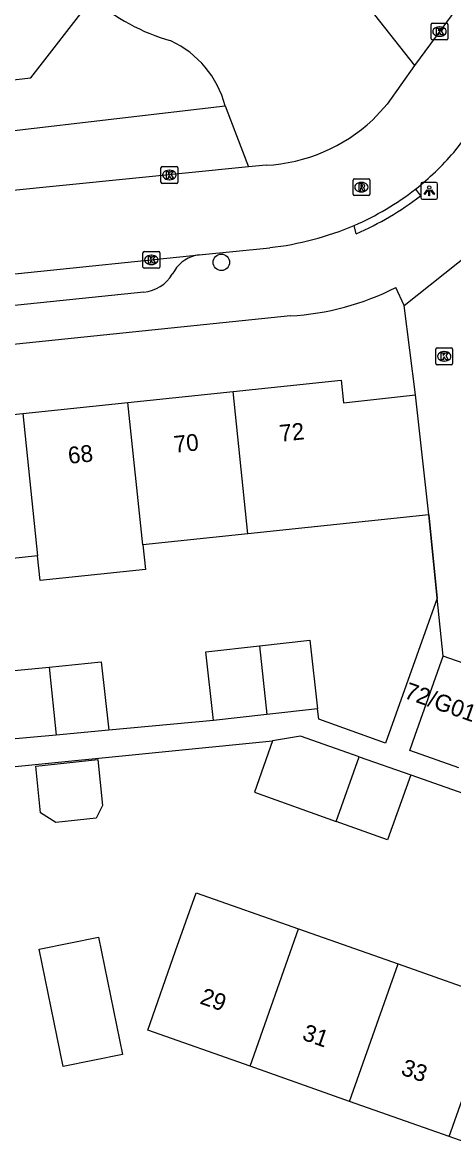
# Model space of a CAD drawing. Extents: x 160557 to 161245, y 385330 to 386505.
# Drawn here: x 160836.9 to 160862.6, y 385939.3 to 386005.8 of the extents above; entities that cross this region are included whole.
import ezdxf

# ---------------------------------------------------------------- set-up
doc = ezdxf.new("R2010")
doc.units = 0
for name, color, linetype in [('IMGEO_Boom', 7, 'Continuous'), ('IMGEO_Groenvoorziening', 7, 'Continuous'), ('IMGEO_Kolk', 7, 'Continuous'), ('IMGEO_Lichtpunt', 7, 'Continuous'), ('IMGEO_Muur', 7, 'Continuous'), ('IMGEO_Pand', 7, 'Continuous'), ('IMGEO_Pand_nummerreeks', 7, 'Continuous'), ('IMGEO_Rijbaan_lokaal_open', 7, 'Continuous'), ('IMGEO_Rioolput', 7, 'Continuous'), ('IMGEO_Voetpad_open', 7, 'Continuous')]:
    doc.layers.add(name, color=color, linetype=linetype)

msp = doc.modelspace()

# ---------------------------------------------------------------- linework, layer by layer
at = {"layer": 'IMGEO_Boom'}
msp.add_circle((160848.786, 385991.504), 0.489, dxfattribs=at)
at = {"layer": 'IMGEO_Groenvoorziening'}
for points in [[(160810.264, 385996.293), (160810.045, 385999.398), (160815.371, 386000), (160837.444, 386002.495), (160841.108, 386007.247)], [(160810.264, 385996.293), (160849.009, 386000.831)]]:
    msp.add_lwpolyline(points, dxfattribs=at)
at = {"layer": 'IMGEO_Kolk'}
for p, q in [((160861.283, 386004.824), (160861.283, 386005.676)), ((160861.358, 386005.75), (160862.21, 386005.75)), ((160861.771, 386005.53), (160861.796, 386005.53)), ((160862.284, 386005.676), (160862.284, 386004.824)), ((160861.794, 386004.97), (160861.769, 386004.97)), ((160862.21, 386004.75), (160861.358, 386004.75)), ((160845.188, 385996.282), (160845.188, 385997.134)), ((160845.263, 385997.208), (160846.115, 385997.208)), ((160845.676, 385996.988), (160845.701, 385996.988)), ((160846.189, 385997.134), (160846.189, 385996.282)), ((160846.115, 385996.208), (160845.263, 385996.208)), ((160845.699, 385996.428), (160845.674, 385996.428)), ((160844.192, 385992.151), (160845.044, 385992.151)), ((160844.117, 385991.225), (160844.117, 385992.077)), ((160844.605, 385991.931), (160844.63, 385991.931)), ((160845.118, 385992.077), (160845.118, 385991.225)), ((160845.044, 385991.151), (160844.192, 385991.151)), ((160844.628, 385991.371), (160844.603, 385991.371)), ((160861.563, 385985.478), (160861.563, 385986.33)), ((160861.638, 385986.404), (160862.49, 385986.404)), ((160862.051, 385986.184), (160862.076, 385986.184)), ((160862.564, 385986.33), (160862.564, 385985.478)), ((160862.074, 385985.624), (160862.049, 385985.624)), ((160862.49, 385985.404), (160861.638, 385985.404))]:
    msp.add_line(p, q, dxfattribs=at)
for points in [[(160861.283, 386004.824), (160861.283, 386005.676)], [(160861.358, 386005.75), (160862.21, 386005.75)], [(160861.604, 386005.45), (160861.727, 386005.45), (160861.727, 386005.299), (160861.857, 386005.45), (160862.021, 386005.45), (160861.875, 386005.299), (160862.028, 386005.05), (160861.876, 386005.05), (160861.791, 386005.214), (160861.727, 386005.147), (160861.727, 386005.05), (160861.604, 386005.05), (160861.604, 386005.45)], [(160862.284, 386005.676), (160862.284, 386004.824)], [(160862.21, 386004.75), (160861.358, 386004.75)], [(160845.188, 385996.282), (160845.188, 385997.134)], [(160845.263, 385997.208), (160846.115, 385997.208)], [(160845.509, 385996.908), (160845.632, 385996.908), (160845.632, 385996.757), (160845.762, 385996.908), (160845.926, 385996.908), (160845.78, 385996.757), (160845.933, 385996.508), (160845.781, 385996.508), (160845.696, 385996.672), (160845.632, 385996.605), (160845.632, 385996.508), (160845.509, 385996.508), (160845.509, 385996.908)], [(160846.189, 385997.134), (160846.189, 385996.282)], [(160846.115, 385996.208), (160845.263, 385996.208)], [(160844.192, 385992.151), (160845.044, 385992.151)], [(160844.117, 385991.225), (160844.117, 385992.077)], [(160844.438, 385991.851), (160844.561, 385991.851), (160844.561, 385991.7), (160844.691, 385991.851), (160844.855, 385991.851), (160844.709, 385991.7), (160844.862, 385991.451), (160844.71, 385991.451), (160844.625, 385991.615), (160844.561, 385991.548), (160844.561, 385991.451), (160844.438, 385991.451), (160844.438, 385991.851)], [(160845.118, 385992.077), (160845.118, 385991.225)], [(160845.044, 385991.151), (160844.192, 385991.151)], [(160861.563, 385985.478), (160861.563, 385986.33)], [(160861.638, 385986.404), (160862.49, 385986.404)], [(160862.564, 385986.33), (160862.564, 385985.478)], [(160861.884, 385986.104), (160862.007, 385986.104), (160862.007, 385985.953), (160862.137, 385986.104), (160862.301, 385986.104), (160862.155, 385985.953), (160862.308, 385985.704), (160862.156, 385985.704), (160862.071, 385985.868), (160862.007, 385985.801), (160862.007, 385985.704), (160861.884, 385985.704), (160861.884, 385986.104)], [(160862.49, 385985.404), (160861.638, 385985.404)]]:
    msp.add_lwpolyline(points, dxfattribs=at)
for centre, start, end in [((160861.36, 386005.674), 91.55205, 178.44795), ((160861.36, 386005.674), 91.55205, 178.44795), ((160862.208, 386005.674), 1.55205, 88.44795), ((160862.208, 386005.674), 1.55205, 88.44795), ((160861.36, 386004.826), 181.55205, 268.44795), ((160861.36, 386004.826), 181.55205, 268.44795), ((160862.208, 386004.826), 271.55205, 358.44795), ((160862.208, 386004.826), 271.55205, 358.44795), ((160845.265, 385997.132), 91.55205, 178.44795), ((160845.265, 385997.132), 91.55205, 178.44795), ((160846.113, 385997.132), 1.55205, 88.44795), ((160846.113, 385997.132), 1.55205, 88.44795), ((160845.265, 385996.284), 181.55205, 268.44795), ((160845.265, 385996.284), 181.55205, 268.44795), ((160846.113, 385996.284), 271.55205, 358.44795), ((160846.113, 385996.284), 271.55205, 358.44795), ((160844.194, 385992.075), 91.55205, 178.44795), ((160844.194, 385992.075), 91.55205, 178.44795), ((160845.042, 385992.075), 1.55205, 88.44795), ((160845.042, 385992.075), 1.55205, 88.44795), ((160844.194, 385991.227), 181.55205, 268.44795), ((160844.194, 385991.227), 181.55205, 268.44795), ((160845.042, 385991.227), 271.55205, 358.44795), ((160845.042, 385991.227), 271.55205, 358.44795), ((160861.64, 385986.328), 91.55205, 178.44795), ((160861.64, 385986.328), 91.55205, 178.44795), ((160862.488, 385986.328), 1.55205, 88.44795), ((160862.488, 385986.328), 1.55205, 88.44795), ((160861.64, 385985.48), 181.55205, 268.44795), ((160861.64, 385985.48), 181.55205, 268.44795), ((160862.488, 385985.48), 271.55205, 358.44795), ((160862.488, 385985.48), 271.55205, 358.44795)]:
    msp.add_arc(centre, 0.0765, start, end, dxfattribs=at)
for centre, major_axis, ratio, start_param, end_param in [((160861.77, 386005.25), (-0.387, 0.002), 0.722429, 4.712389, 7.853982), ((160861.795, 386005.25), (-0.39, 0.002), 0.717154, 1.570796, 4.712389), ((160845.675, 385996.708), (-0.387, 0.002), 0.722429, 4.712389, 7.853982), ((160845.7, 385996.708), (-0.39, 0.002), 0.717154, 1.570796, 4.712389), ((160844.604, 385991.651), (-0.387, 0.002), 0.722429, 4.712389, 7.853982), ((160844.629, 385991.651), (-0.39, 0.002), 0.717154, 1.570796, 4.712389), ((160862.05, 385985.904), (-0.387, 0.002), 0.722429, 4.712389, 7.853982), ((160862.075, 385985.904), (-0.39, 0.002), 0.717154, 1.570796, 4.712389)]:
    msp.add_ellipse(centre, major_axis=major_axis, ratio=ratio, start_param=start_param, end_param=end_param, dxfattribs=at)
at = {"layer": 'IMGEO_Lichtpunt'}
for p, q in [((160860.674, 385996.164), (160860.674, 385995.357)), ((160860.674, 385996.164), (160860.674, 385995.357)), ((160861.576, 385996.259), (160860.768, 385996.259)), ((160861.576, 385996.259), (160860.768, 385996.259)), ((160861.67, 385995.357), (160861.67, 385996.164)), ((160861.67, 385995.357), (160861.67, 385996.164)), ((160860.768, 385995.263), (160861.576, 385995.263)), ((160860.768, 385995.263), (160861.576, 385995.263))]:
    msp.add_line(p, q, dxfattribs=at)
for points in [[(160861.048, 385995.828), (160861.087, 385995.8), (160860.899, 385995.538), (160860.861, 385995.565), (160861.048, 385995.828)], [(160861.15, 385995.78), (160861.197, 385995.78), (160861.197, 385995.458), (160861.15, 385995.458), (160861.15, 385995.78)], [(160861.26, 385995.8), (160861.298, 385995.827), (160861.485, 385995.565), (160861.446, 385995.537), (160861.26, 385995.8)]]:
    msp.add_lwpolyline(points, dxfattribs=at)
msp.add_circle((160861.173, 385995.962), 0.0994, dxfattribs=at)
for centre, start, end in [((160860.768, 385996.164), 90, 180), ((160860.768, 385996.164), 90, 180), ((160861.576, 385996.164), 0, 90), ((160861.576, 385996.164), 0, 90), ((160860.768, 385995.357), 180, 270), ((160860.768, 385995.357), 180, 270), ((160861.576, 385995.357), 270, 0), ((160861.576, 385995.357), 270, 360)]:
    msp.add_arc(centre, 0.0946, start, end, dxfattribs=at)
at = {"layer": 'IMGEO_Muur'}
for points in [[(160861.144, 385976.456), (160861.645, 385971.496)], [(160861.645, 385971.496), (160858.563, 385962.869)]]:
    msp.add_lwpolyline(points, dxfattribs=at)
at = {"layer": 'IMGEO_Pand'}
for points in [[(160849.487, 385983.818), (160855.932, 385984.491), (160856.074, 385983.14), (160860.359, 385983.611)], [(160843.218, 385983.163), (160849.487, 385983.818)], [(160850.373, 385975.327), (160849.487, 385983.818)], [(160861.144, 385976.456), (160860.359, 385983.611)], [(160836.949, 385982.508), (160843.218, 385983.163)], [(160844.104, 385974.67), (160843.218, 385983.163)], [(160830.68, 385981.854), (160836.949, 385982.508)], [(160836.949, 385982.508), (160837.836, 385974.012)], [(160861.144, 385976.456), (160850.373, 385975.327)], [(160850.373, 385975.327), (160844.104, 385974.67)], [(160844.104, 385974.67), (160844.257, 385973.205), (160837.989, 385972.55), (160837.836, 385974.012)], [(160837.836, 385974.012), (160831.567, 385973.355)], [(160851.067, 385968.668), (160854.059, 385969.003), (160854.517, 385964.909)], [(160848.319, 385964.215), (160847.861, 385968.309), (160851.067, 385968.668)], [(160851.067, 385968.668), (160851.495, 385964.571)], [(160838.526, 385967.397), (160841.634, 385967.701), (160842.089, 385963.638)], [(160862.927, 385961.397), (160860.013, 385962.422), (160860.334, 385963.334), (160861.993, 385968.05)], [(160864.907, 385967.025), (160861.993, 385968.05)], [(160835.849, 385963.06), (160835.398, 385967.092), (160838.526, 385967.397)], [(160838.526, 385967.397), (160838.948, 385963.347)], [(160854.517, 385964.909), (160851.495, 385964.571)], [(160851.495, 385964.571), (160848.319, 385964.215)], [(160842.089, 385963.638), (160838.948, 385963.347)], [(160838.948, 385963.347), (160835.849, 385963.06)], [(160851.843, 385963.002), (160850.755, 385959.949), (160855.636, 385958.193)], [(160856.999, 385962.054), (160853.51, 385963.283), (160851.843, 385963.002)], [(160837.724, 385961.499), (160841.426, 385961.884), (160841.71, 385959.151), (160841.328, 385958.389), (160838.916, 385958.137), (160838.015, 385958.71), (160837.724, 385961.499)], [(160855.636, 385958.193), (160856.999, 385962.054)], [(160856.999, 385962.054), (160860.069, 385960.973)], [(160860.069, 385960.973), (160858.687, 385957.096), (160855.636, 385958.193)], [(160850.495, 385943.621), (160844.396, 385945.773), (160846.06, 385950.488), (160847.284, 385953.956), (160853.382, 385951.804)], [(160850.495, 385943.621), (160853.382, 385951.804)], [(160853.382, 385951.804), (160859.317, 385949.71)], [(160837.928, 385950.586), (160841.461, 385951.312), (160842.896, 385944.323), (160839.364, 385943.597), (160837.928, 385950.586)], [(160856.43, 385941.526), (160859.317, 385949.71)], [(160859.317, 385949.71), (160865.253, 385947.615)], [(160862.365, 385939.432), (160865.253, 385947.615)], [(160856.43, 385941.526), (160850.495, 385943.621)], [(160862.365, 385939.432), (160856.43, 385941.526)], [(160868.3, 385937.337), (160862.365, 385939.432)]]:
    msp.add_lwpolyline(points, dxfattribs=at)
at = {"layer": 'IMGEO_Rijbaan_lokaal_open'}
for points in [[(160874.196, 386022.067), (160860.296, 386003.233)], [(160860.296, 386003.233), (160858.671, 386000.925), (160857.806, 386000)], [(160862.629, 385998.05), (160864.17, 386000.025), (160864.278, 386000.17)], [(160850.396, 385997.184), (160810.482, 385993.187)], [(160851.454, 385997.29), (160850.396, 385997.184)], [(160847.456, 385991.944), (160851.678, 385992.378)], [(160788.954, 385985.976), (160801.932, 385987.281), (160825.874, 385989.726), (160847.456, 385991.944)], [(160859.687, 385988.936), (160863.654, 385992.093)], [(160860.359, 385983.611), (160859.687, 385988.936)], [(160861.645, 385971.496), (160861.144, 385976.456)], [(160861.993, 385968.05), (160861.645, 385971.496)]]:
    msp.add_lwpolyline(points, dxfattribs=at)
for centre, radius, start, end in [((160850.956, 386007.256), 9.978, 272.85933, 313.35047), ((160850.31, 386008.607), 16.224, 308.25527, 319.4054), ((160849.778, 386009.535), 17.283, 293.64451, 307.73606), ((160849.601, 386010.48), 18.22, 276.54673, 292.96281)]:
    msp.add_arc(centre, radius, start, end, dxfattribs=at)
at = {"layer": 'IMGEO_Rioolput'}
for p, q in [((160856.631, 385995.556), (160856.631, 385996.408)), ((160856.706, 385996.482), (160857.558, 385996.482)), ((160857.119, 385996.262), (160857.144, 385996.262)), ((160857.632, 385996.408), (160857.632, 385995.556)), ((160857.558, 385995.482), (160856.706, 385995.482)), ((160857.142, 385995.702), (160857.117, 385995.702))]:
    msp.add_line(p, q, dxfattribs=at)
for points in [[(160856.631, 385995.556), (160856.631, 385996.408)], [(160856.706, 385996.482), (160857.558, 385996.482)], [(160857.22, 385996.18), (160856.968, 385996.182), (160856.968, 385995.782)], [(160857.632, 385996.408), (160857.632, 385995.556)], [(160857.558, 385995.482), (160856.706, 385995.482)], [(160856.968, 385995.782), (160857.092, 385995.782), (160857.092, 385995.944), (160857.103, 385995.944)], [(160857.146, 385996.101), (160857.092, 385996.101), (160857.092, 385996.02)], [(160857.092, 385996.02), (160857.144, 385996.02)], [(160857.15, 385995.915), (160857.221, 385995.782), (160857.361, 385995.782), (160857.296, 385995.908)]]:
    msp.add_lwpolyline(points, dxfattribs=at)
for centre, radius, start, end in [((160856.708, 385996.406), 0.0765, 91.55205, 178.44795), ((160856.708, 385996.406), 0.0765, 91.55205, 178.44795), ((160857.219, 385996.07), 0.109, 350.36119, 89.41601), ((160857.556, 385996.406), 0.0765, 1.55205, 88.44795), ((160857.556, 385996.406), 0.0765, 1.55205, 88.44795), ((160856.708, 385995.558), 0.0765, 181.55205, 268.44795), ((160856.708, 385995.558), 0.0765, 181.55205, 268.44795), ((160857.102, 385995.891), 0.0533, 26.02933, 88.69889), ((160857.128, 385996.209), 0.19, 274.7715, 282.96867), ((160857.152, 385996.005), 0.0964, 77.00612, 93.18647), ((160857.166, 385996.062), 0.0378, 276.66336, 79.67722), ((160857.217, 385996.07), 0.112, 277.58423, 350.98172), ((160857.201, 385995.855), 0.108, 29.51342, 73.79051), ((160857.556, 385995.558), 0.0765, 271.55205, 358.44795), ((160857.556, 385995.558), 0.0765, 271.55205, 358.44795)]:
    msp.add_arc(centre, radius, start, end, dxfattribs=at)
for centre, major_axis, ratio, start_param, end_param in [((160857.118, 385995.982), (-0.387, 0.002), 0.722429, 4.712389, 7.853982), ((160857.143, 385995.982), (-0.39, 0.002), 0.717154, 1.570796, 4.712389)]:
    msp.add_ellipse(centre, major_axis=major_axis, ratio=ratio, start_param=start_param, end_param=end_param, dxfattribs=at)
at = {"layer": 'IMGEO_Voetpad_open'}
for points in [[(160857.022, 386007.394), (160860.296, 386003.233)], [(160849.009, 386000.831), (160849.325, 386000), (160850.396, 385997.184)], [(160860.355, 385995.867), (160860.645, 385995.46)], [(160856.827, 385993.209), (160856.709, 385993.703)], [(160845.993, 385991.005), (160845.862, 385990.792)], [(160844.175, 385989.732), (160826.064, 385987.871), (160802.12, 385985.425), (160792.445, 385984.458)], [(160859.687, 385988.936), (160859.181, 385990.012)], [(160852.902, 385988.314), (160784.881, 385981.295)], [(160861.645, 385971.496), (160858.563, 385962.869), (160854.6, 385964.296), (160854.517, 385964.909)], [(160848.319, 385964.215), (160842.089, 385963.638)], [(160829.319, 385960.753), (160851.843, 385963.002)], [(160860.069, 385960.973), (160865.99, 385958.889)]]:
    msp.add_lwpolyline(points, dxfattribs=at)
for centre, radius, start, end in [((160849.114, 386016.345), 12.119, 228.65351, 254.06209), ((160843.291, 385999.334), 5.911, 14.67413, 65.03328), ((160849.799, 386009.492), 17.735, 293.34441, 307.70072), ((160847.696, 385989.961), 1.998, 96.89944, 148.48784), ((160843.945, 385991.971), 2.25, 275.86725, 328.41786), ((160852.037, 386003.972), 15.682, 273.16265, 297.10191)]:
    msp.add_arc(centre, radius, start, end, dxfattribs=at)

# ---------------------------------------------------------------- texts
at = {"layer": 'IMGEO_Pand_nummerreeks'}
for s, rotation, p in [('72', 5.96218, (160852.297, 385980.814)), ('70', 5.96218, (160846.003, 385980.156)), ('68', 5.96218, (160839.702, 385979.498)), ('72/G01', 340.45265, (160859.617, 385965.572)), ('29', 340.56188, (160847.45, 385947.368)), ('31', 340.56188, (160853.547, 385945.216)), ('33', 340.56188, (160859.43, 385943.14))]:
    msp.add_text(s, height=1, rotation=rotation, dxfattribs=at).set_placement(p)

doc.saveas('drawing.dxf')
